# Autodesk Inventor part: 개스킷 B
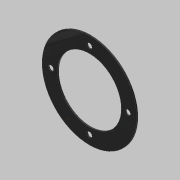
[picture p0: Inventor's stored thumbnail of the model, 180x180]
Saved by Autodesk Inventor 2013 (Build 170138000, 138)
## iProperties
Created: 2019-10
Part Number: 개스킷 B
Material: 고무
Document SubType Name: Modeling
Designer: mduedu
Density: 1 g/cm^3
Author: mduedu
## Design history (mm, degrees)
sketch "스케치1"
  geometry: C1 r 40 at (0, 0); C2 r 27 at (0, 0); 1 further point
  constraints: 2 centre point, 2 coincident
  dimensions: "d0" = 80 diameter of C1; "d1" = 54 diameter of C2
extrude "돌출1" new body sketch "스케치1" distance "d2" = 1; taper "d3" = 0 deg
sketch "스케치2" dims "d4" = 65
  geometry: C1 r 2.25 at (0, 32.5); 2 further points
  constraints: 2 vertical alignment, 1 centre point, 1 coincident, 2 other
  dimensions: "d5" = 4.5 diameter of C1
extrude "돌출2" cut sketch "스케치2" stored distance "d6" = 1; taper "d7" = 0 deg
node "솔리드1"
pattern_circular "원형 패턴1" dims angle "d9" = 360 deg
